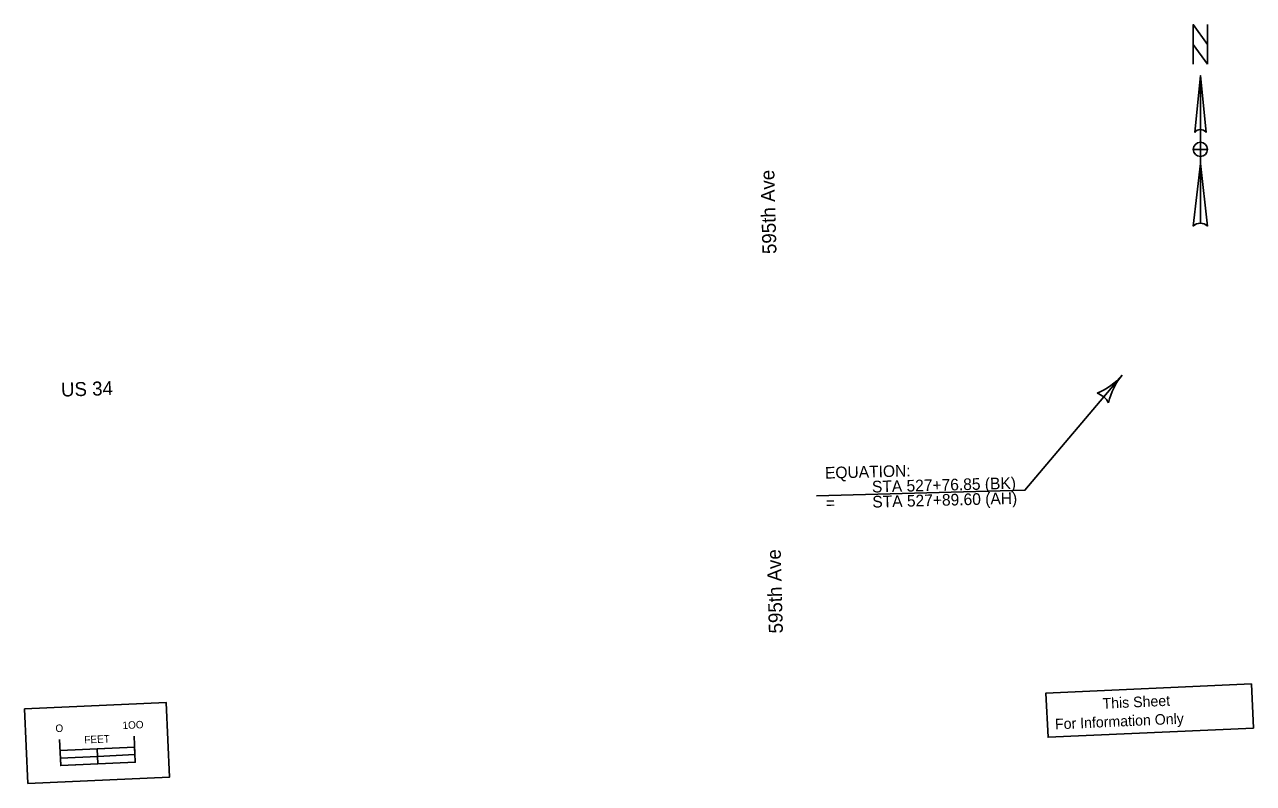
# Model space of a CAD drawing. Extents: x 22712865 to 22760106, y 6235088 to 6238602.
# Drawn here: x 22728976 to 22730623, y 6235591 to 6236608 of the extents above; entities that cross this region are included whole.
import ezdxf

# ---------------------------------------------------------------- set-up
doc = ezdxf.new("R2010")
doc.units = 0
for name, color, linetype in [('_CIVIL_CONSTRUCTION', 7, 'Continuous'), ('Contours Major', 7, 'Continuous'), ('Default', 7, 'Continuous'), ('Entrance', 7, 'Continuous')]:
    doc.layers.add(name, color=color, linetype=linetype)

msp = doc.modelspace()

# ---------------------------------------------------------------- linework, layer by layer
at = {"layer": '_CIVIL_CONSTRUCTION'}
msp.add_line((22729074, 6235617.4), (22729073.1, 6235637.4), dxfattribs=at)
msp.add_line((22729074, 6235617.4), (22729073.1, 6235637.4), dxfattribs=at)
for points in [[(22728975.6, 6235691), (22729165.4, 6235699.6), (22729169.9, 6235599.7), (22728980.1, 6235591.1)], [(22728980.1, 6235591.1), (22728975.6, 6235691), (22729165.4, 6235699.6), (22729169.9, 6235599.7)], [(22729073.6, 6235627.4), (22729123.5, 6235629.7), (22729123.1, 6235639.6), (22729073.1, 6235637.4)], [(22729024.1, 6235615.1), (22729074, 6235617.4), (22729073.6, 6235627.4), (22729023.6, 6235625.2)]]:
    msp.add_lwpolyline(points, close=True, dxfattribs=at)
for points in [[(22729022.5, 6235650.1), (22729024.1, 6235615.1), (22729124, 6235619.6), (22729122.4, 6235654.6)], [(22729023.2, 6235635.1), (22729123.1, 6235639.6)]]:
    msp.add_lwpolyline(points, dxfattribs=at)
at = {"layer": 'Contours Major'}
msp.add_lwpolyline([(22730446.9, 6236138.4), (22730316.5, 6235984.1), (22730037.2, 6235976.8)], dxfattribs=at)
for centre, radius, start, end in [((22730381.9, 6236193.3), 85, 291.7468, 319.8193), ((22730511.8, 6236083.6), 85, 139.8193, 167.8918), ((22730400.9, 6236084), 32.8, 32.0859, 67.5526)]:
    msp.add_arc(centre, radius, start, end, dxfattribs=at)
at = {"layer": 'Entrance'}
for p, q in [((22730551.6, 6236539.8), (22730559.2, 6236463.7)), ((22730551.6, 6236539.8), (22730551.6, 6236342)), ((22730544, 6236463.7), (22730544, 6236463.7)), ((22730544.3, 6236464.4), (22730545.7, 6236466)), ((22730551.6, 6236431.4), (22730551.6, 6236431.4)), ((22730542.1, 6236338.2), (22730551.6, 6236421.9))]:
    msp.add_line(p, q, dxfattribs=at)
for points in [[(22730561.1, 6236555), (22730542.1, 6236581.6), (22730542.1, 6236608.2), (22730561.1, 6236581.6)], [(22730347.4, 6235653.1), (22730622.7, 6235665.4), (22730620.1, 6235724.4), (22730344.7, 6235712.1)], [(22730344.7, 6235712.1), (22730620.1, 6235724.4), (22730622.7, 6235665.4), (22730347.4, 6235653.1)]]:
    msp.add_lwpolyline(points, close=True, dxfattribs=at)
for points in [[(22730542.1, 6236555), (22730542.1, 6236608.2), (22730561.1, 6236581.6), (22730561.1, 6236608.2)], [(22730544, 6236463.7), (22730551.6, 6236539.8), (22730551.6, 6236467.5)], [(22730561.1, 6236440.9), (22730551.6, 6236440.9), (22730551.6, 6236450.4)], [(22730551.6, 6236431.4), (22730551.6, 6236440.9), (22730542.1, 6236440.9)], [(22730551.6, 6236342), (22730551.6, 6236421.9), (22730561.1, 6236338.2)]]:
    msp.add_lwpolyline(points, dxfattribs=at)
for centre, radius, start, end in [((22730551.6, 6236458), 9.51, 90.0204, 143.1257), ((22730551.6, 6236458), 9.5, 36.8481, 90.0218), ((22730551.6, 6236440.9), 9.51, 90, 180), ((22730551.6, 6236440.9), 9.51, 0, 90), ((22730551.6, 6236440.9), 9.51, 180, 270), ((22730551.6, 6236440.9), 9.51, 270, 360), ((22730551.6, 6236328.2), 13.8, 89.9894, 133.619), ((22730551.6, 6236328.2), 13.8, 46.4021, 90.0006)]:
    msp.add_arc(centre, radius, start, end, dxfattribs=at)

# ---------------------------------------------------------------- texts
at = {"layer": '_CIVIL_CONSTRUCTION'}
for s, p in [('O', (22729017.2, 6235659.9)), ('O', (22729017.2, 6235659.9)), ('1OO', (22729107.1, 6235663.9)), ('1OO', (22729107.1, 6235663.9)), ('FEET', (22729055.9, 6235644.6))]:
    msp.add_text(s, height=10, rotation=2.5727, dxfattribs=at).set_placement(p)
at = {"layer": 'Contours Major'}
for s, height, p in [('EQUATION:', 15.6, (22730048.7, 6235999.6)), ('STA 527+76.85 (BK)', 15.601, (22730111.6, 6235981)), ('=', 15.6, (22730049.8, 6235959.2)), ('STA 527+89.60 (AH)', 15.601, (22730112.1, 6235960.8))]:
    msp.add_text(s, height=height, rotation=1.5081, dxfattribs=at).set_placement(p)
at = {"layer": 'Default'}
for s, rotation, p in [('595th Ave', 91.5347, (22729983.5, 6236300.9)), ('US 34', 1.7877, (22729024.7, 6236109.5)), ('595th Ave', 91.5347, (22729992.1, 6235792.4))]:
    msp.add_text(s, height=18.75, rotation=rotation, dxfattribs=at).set_placement(p)
at = {"layer": 'Entrance'}
for s, height, p in [('This Sheet', 14.17, (22730420.8, 6235691.2)), ('For Information Only', 14.175, (22730357.1, 6235663.5))]:
    msp.add_text(s, height=height, rotation=2.5727, dxfattribs=at).set_placement(p)

doc.saveas('drawing.dxf')
